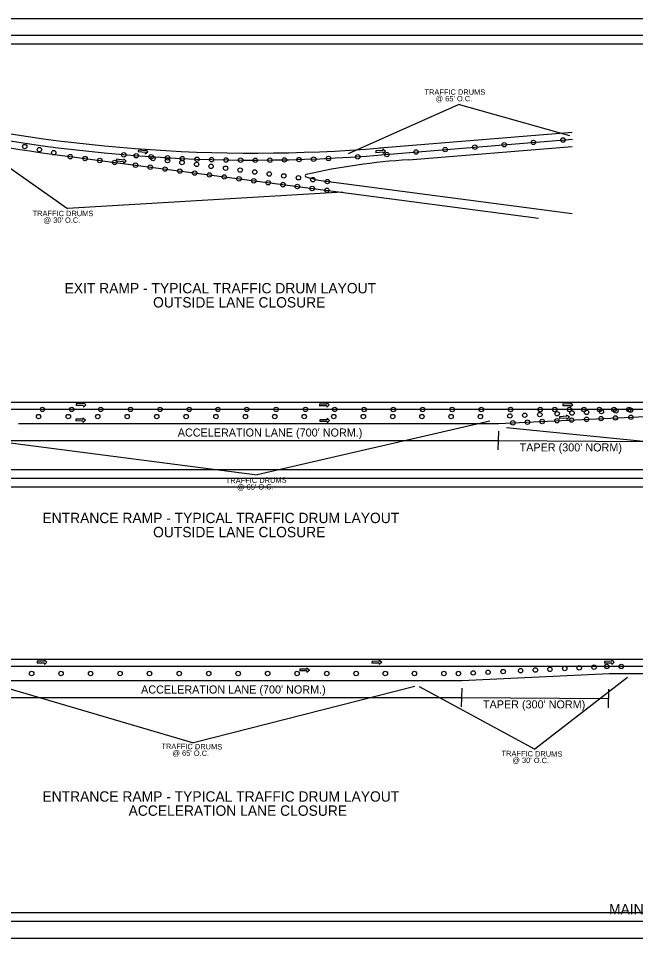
# Model space of a CAD drawing. Extents: x 13528 to 25043, y 7635 to 10612.
# Drawn here: x 18181 to 18896, y 9545 to 10612 of the extents above; entities that cross this region are included whole.
import ezdxf

# ---------------------------------------------------------------- set-up
doc = ezdxf.new("R2010")
doc.units = 0
for name, color, linetype in [('Default', 7, 'Continuous'), ('R_Border', 7, 'Continuous'), ('R_Border Plan-Plan', 7, 'Continuous'), ('R_Draft', 7, 'Continuous'), ('R_Revision Date Text', 7, 'Continuous')]:
    doc.layers.add(name, color=color, linetype=linetype)

# ---------------------------------------------------------------- blocks, each defined once
blk = doc.blocks.new('DOT')
at = {"layer": 'Default'}
blk.add_circle((-0.4, -0.3), 3.75, dxfattribs=at)
blk = doc.blocks.new('SARROW')
at = {"layer": 'Default'}
for p, q in [((15.6, 3.2), (-13.8, 3.2)), ((-13.8, 3.2), (-13.8, -2.8)), ((15.6, 8.2), (15.6, 3.2)), ((15.6, 8.2), (26, 0.2)), ((26, 0.2), (15.6, -7.8)), ((15.6, -2.8), (-13.8, -2.8)), ((15.6, -2.8), (15.6, -7.8))]:
    blk.add_line(p, q, dxfattribs=at)

msp = doc.modelspace()

# ---------------------------------------------------------------- linework, layer by layer
at = {"layer": 'Default'}
for p, q in [((18599.8, 10461.4), (18822.8, 10479.6)), ((18601.5, 10453.3), (18823.3, 10471.5)), ((18217.1, 10454.7), (18783.8, 10380.1)), ((18633.3, 10447.7), (18822.8, 10463.2)), ((18534.5, 10423.2), (18822.8, 10385.2)), ((18002.2, 10166.6), (19044, 10166.6)), ((18002, 10158.4), (19043.8, 10158.4)), ((18737.5, 10142.1), (18908.1, 10150.2)), ((18181, 10142), (18737.5, 10142.1)), ((18737.4, 10133.1), (18736.8, 10111.3)), ((18087.9, 10122.2), (18737.1, 10122.2)), ((17907.8, 9868.7), (19009.2, 9868.7)), ((17907.6, 9860.5), (19009, 9860.5)), ((18695, 9844.2), (18865.7, 9852.3)), ((18865.7, 9852.3), (19008.8, 9852.3)), ((18138.5, 9844.2), (18695, 9844.2)), ((18694.9, 9835.2), (18694.4, 9813.5)), ((18045.4, 9824.3), (18694.6, 9824.3)), ((18865.1, 9834), (18864.6, 9812.3))]:
    msp.add_line(p, q, dxfattribs=at)
for centre, major_axis, start_param, end_param in [((18454.4, 13048.2), (0, 2600.9), 2.945637, 3.209664), ((18454.4, 13048.2), (0, 2592.8), 2.945637, 3.209664), ((18454.4, 13048.2), (0, 2609.1), 2.94688, 3.032274), ((18680.7, 9372.1), (0, 1077.1), 0.052832, 0.186328), ((18514.6, 10429.2), (0, 1.36), 0.197268, 2.831699), ((18548, 10570.7), (0, -148.3), 6.00653, 6.174382)]:
    msp.add_ellipse(centre, major_axis=major_axis, ratio=0.833333, start_param=start_param, end_param=end_param, dxfattribs=at)
at = {"layer": 'R_Border'}
for p, q in [((18563.8, 10454.9), (18691.1, 10511.6)), ((18820.1, 10475.3), (18691.1, 10511.6)), ((18111.7, 10480), (18237.7, 10391.1)), ((18315.9, 10450.8), (18315.5, 10450.4)), ((18556.6, 10410), (18237.7, 10391.1)), ((18727.5, 10144.5), (18457.7, 10082.5)), ((18060.9, 10134), (18457.7, 10082.5)), ((18747, 10137.5), (18946.7, 10117.4)), ((18737.1, 10122.2), (18907.3, 10121)), ((18887, 9847.7), (18779.8, 9764.3)), ((18155.5, 9838.8), (18383.8, 9771.7)), ((18640.4, 9836.9), (18383.8, 9771.7)), ((18645.6, 9837), (18779.8, 9764.3)), ((18694.6, 9824.3), (18864.9, 9823.1))]:
    msp.add_line(p, q, dxfattribs=at)
at = {"layer": 'R_Border Plan-Plan'}
msp.add_line((17653.6, 10078.4), (19234.5, 10078.4), dxfattribs=at)
at = {"layer": 'R_Draft'}
for p, q in [((17653.6, 10592.1), (19234.5, 10592.1)), ((18416.2, 10590.8), (18416.2, 10590.8)), ((18416.2, 10590.8), (18416.2, 10590.8)), ((19234.5, 9564.8), (17653.6, 9564.8))]:
    msp.add_line(p, q, dxfattribs=at)
at = {"layer": 'R_Revision Date Text'}
for points in [[(17591.6, 10611.5), (19258.3, 10611.5), (19258.3, 9544.9), (17591.6, 9544.9)], [(19224.5, 10088.4), (17663.6, 10088.4), (17663.6, 10582.1), (18911.3, 10582.1), (18911.3, 10532.7), (18999, 10532.7), (19119.5, 10532.7), (19119.5, 10421), (19224.5, 10421)], [(17663.6, 10582.1), (18911.3, 10582.1), (18911.3, 10532.7), (18999, 10532.7), (19119.5, 10532.7), (19119.5, 10421), (19224.5, 10421), (19224.5, 9574.8), (17663.6, 9574.8)], [(17663.6, 10068.4), (19224.5, 10068.4), (19224.5, 9574.8), (17663.6, 9574.8)]]:
    msp.add_lwpolyline(points, close=True, dxfattribs=at)

# ---------------------------------------------------------------- block references
at = {"layer": 'R_Border', "xscale": 0.6809210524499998, "yscale": 0.6809210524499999}
for p in [(18188.6, 10463.2), (18710.4, 10462.5), (18744.5, 10465.3), (18778.3, 10468), (18812.6, 10470.8), (18205.6, 10459.6), (18222.2, 10456.1), (18241.3, 10451.5), (18303.4, 10453.6), (18317.8, 10452.6), (18335.1, 10451.3), (18574.6, 10451.3), (18608.4, 10453.9), (18642.2, 10456.9), (18676, 10459.7), (18258.5, 10449.3), (18275.6, 10447), (18292.8, 10444.8), (18317, 10441.6), (18337.2, 10449.2), (18354.1, 10447), (18354.2, 10450.1), (18370.9, 10444.7), (18371.2, 10449.2), (18387.8, 10442.5), (18388.3, 10448.5), (18405.2, 10448), (18422, 10447.6), (18438.9, 10447.4), (18455.8, 10447.3), (18472.8, 10447.4), (18489.6, 10447.7), (18506.5, 10448.1), (18523.5, 10448.6), (18540.7, 10449.4), (18334.1, 10439.3), (18351.3, 10437.1), (18368.4, 10434.8), (18385.6, 10432.5), (18402.7, 10430.3), (18404.6, 10440.3), (18421.4, 10438.1), (18438.3, 10435.9), (18455.2, 10433.7), (18472, 10431.4), (18419.9, 10428), (18437, 10425.8), (18454.1, 10423.5), (18470.8, 10421.3), (18488.8, 10429.2), (18505.9, 10427), (18522.6, 10424.8), (18539.4, 10422.6), (18488, 10419), (18504.6, 10416.9), (18521.8, 10414.6), (18538.9, 10412.5)]:
    msp.add_blockref('DOT', p, dxfattribs=at)
at = {"layer": 'R_Border'}
for name, p, xscale, yscale, rotation in [('SARROW', (18323.8, 10457.3), 0.2841392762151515, 0.3399546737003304, -5.657384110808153), ('SARROW', (18599.3, 10457.1), 0.2840002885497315, 0.3401210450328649, 4.632677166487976), ('SARROW', (18298.6, 10446.7), 0.2843459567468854, 0.3397075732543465, -6.906452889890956), ('SARROW', (18251.9, 10163.6), 0.2839678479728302, 0.3401599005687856, -0.3179055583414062), ('SARROW', (18534, 10163.4), 0.2840325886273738, 0.3400823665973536, 0.21294869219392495), ('SARROW', (18816.2, 10163.5), 0.2839581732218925, 0.3401714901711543, -0.402879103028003), ('DOT', (18209.1, 10158.5), 0.6809210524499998, 0.6809210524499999, -4.676990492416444), ('DOT', (18243, 10158.5), 0.6809210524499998, 0.6809210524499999, -4.676990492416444), ('DOT', (18276.7, 10158.5), 0.6809210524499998, 0.6809210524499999, -4.676990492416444), ('DOT', (18311.2, 10158.5), 0.6809210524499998, 0.6809210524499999, -4.676990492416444), ('DOT', (18345.5, 10158.5), 0.6809210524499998, 0.6809210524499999, -4.676990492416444), ('DOT', (18379.3, 10158.5), 0.6809210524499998, 0.6809210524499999, -4.676990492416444), ('DOT', (18412.6, 10158.5), 0.6809210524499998, 0.6809210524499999, -4.676990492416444), ('DOT', (18446, 10158.5), 0.6809210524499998, 0.6809210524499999, -4.676990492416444), ('DOT', (18480.1, 10158.5), 0.6809210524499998, 0.6809210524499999, -4.676990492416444), ('DOT', (18514.1, 10158.5), 0.6809210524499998, 0.6809210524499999, -4.676990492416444), ('DOT', (18547.9, 10158.5), 0.6809210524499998, 0.6809210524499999, -4.676990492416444), ('DOT', (18582, 10158.4), 0.6809210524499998, 0.6809210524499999, -4.676990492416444), ('DOT', (18615.9, 10158.4), 0.6809210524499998, 0.6809210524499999, -4.676990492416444), ('DOT', (18649.8, 10158.4), 0.6809210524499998, 0.6809210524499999, -4.676990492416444), ('DOT', (18684.1, 10158.4), 0.6809210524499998, 0.6809210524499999, -4.676990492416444), ('DOT', (18717.9, 10158.4), 0.6809210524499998, 0.6809210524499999, -4.676990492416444), ('DOT', (18751.8, 10158.4), 0.6809210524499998, 0.6809210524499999, -4.676990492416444), ('DOT', (18785.7, 10152.5), 0.6809210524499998, 0.6809210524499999, -4.676990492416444), ('DOT', (18786.2, 10158.4), 0.6809210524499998, 0.6809210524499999, -4.676990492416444), ('DOT', (18803.1, 10158.4), 0.6809210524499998, 0.6809210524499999, -4.676990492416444), ('DOT', (18805.8, 10153.5), 0.6809210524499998, 0.6809210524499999, -4.676990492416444), ('DOT', (18820, 10158.4), 0.6809210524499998, 0.6809210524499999, -4.676990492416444), ('DOT', (18823, 10154.3), 0.6809210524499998, 0.6809210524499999, -4.676990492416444), ('DOT', (18836.9, 10158.4), 0.6809210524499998, 0.6809210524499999, -4.676990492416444), ('DOT', (18839.9, 10155.1), 0.6809210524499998, 0.6809210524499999, -4.676990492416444), ('DOT', (18854.8, 10158.4), 0.6809210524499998, 0.6809210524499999, -4.676990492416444), ('DOT', (18857.1, 10155.9), 0.6809210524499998, 0.6809210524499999, -4.676990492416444), ('DOT', (18871.7, 10158.4), 0.6809210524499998, 0.6809210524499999, -4.676990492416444), ('DOT', (18873.9, 10156.7), 0.6809210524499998, 0.6809210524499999, -4.676990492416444), ('DOT', (18889, 10158.4), 0.6809210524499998, 0.6809210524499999, -4.676990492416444), ('DOT', (18891, 10157.6), 0.6809210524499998, 0.6809210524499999, -4.676990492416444), ('DOT', (18204.7, 10150.2), 0.6809210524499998, 0.6809210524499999, -4.676990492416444), ('DOT', (18239.1, 10150.2), 0.6809210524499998, 0.6809210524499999, -4.676990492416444), ('SARROW', (18251.4, 10145.8), 0.2839678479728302, 0.3401599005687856, -0.3179055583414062), ('DOT', (18273.2, 10150.2), 0.6809210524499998, 0.6809210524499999, -4.676990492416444), ('DOT', (18307.4, 10150.2), 0.6809210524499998, 0.6809210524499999, -4.676990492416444), ('DOT', (18341.6, 10150.2), 0.6809210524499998, 0.6809210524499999, -4.676990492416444), ('DOT', (18375.7, 10150.2), 0.6809210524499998, 0.6809210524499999, -4.676990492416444), ('DOT', (18410.2, 10150.2), 0.6809210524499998, 0.6809210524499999, -4.676990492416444), ('DOT', (18444.4, 10150.2), 0.6809210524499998, 0.6809210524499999, -4.676990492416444), ('DOT', (18478.4, 10150.2), 0.6809210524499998, 0.6809210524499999, -4.676990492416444), ('DOT', (18512.6, 10150.2), 0.6809210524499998, 0.6809210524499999, -4.676990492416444), ('SARROW', (18534.3, 10145.2), 0.2840325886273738, 0.3400823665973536, 0.21294869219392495), ('DOT', (18546.8, 10150.2), 0.6809210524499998, 0.6809210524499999, -4.676990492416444), ('DOT', (18581.1, 10150.2), 0.6809210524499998, 0.6809210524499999, -4.676990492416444), ('DOT', (18615.2, 10150.2), 0.6809210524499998, 0.6809210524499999, -4.676990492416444), ('DOT', (18649.1, 10150.2), 0.6809210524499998, 0.6809210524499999, -4.676990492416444), ('DOT', (18682.9, 10150.2), 0.6809210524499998, 0.6809210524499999, -4.676990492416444), ('DOT', (18716.9, 10150.2), 0.6809210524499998, 0.6809210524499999, -4.676990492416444), ('DOT', (18751, 10150.9), 0.6809210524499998, 0.6809210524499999, -4.676990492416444), ('DOT', (18754.5, 10142.9), 0.6809210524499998, 0.6809210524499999, -4.676990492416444), ('DOT', (18754.5, 10142.9), 0.6809210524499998, 0.6809210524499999, -4.676990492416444), ('DOT', (18768.2, 10151.7), 0.6809210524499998, 0.6809210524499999, -4.676990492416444), ('DOT', (18771.4, 10143.7), 0.6809210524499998, 0.6809210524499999, -4.676990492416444), ('DOT', (18788.4, 10144.5), 0.6809210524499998, 0.6809210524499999, -4.676990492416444), ('DOT', (18805.6, 10145.3), 0.6809210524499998, 0.6809210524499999, -4.676990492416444), ('SARROW', (18812.3, 10149), 0.2846173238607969, 0.33938368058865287, 3.589093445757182), ('DOT', (18822.6, 10146.1), 0.6809210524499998, 0.6809210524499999, -4.676990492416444), ('DOT', (18839.9, 10147), 0.6809210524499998, 0.6809210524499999, -4.676990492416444), ('DOT', (18856.7, 10147.8), 0.6809210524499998, 0.6809210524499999, -4.676990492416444), ('DOT', (18873.4, 10148.6), 0.6809210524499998, 0.6809210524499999, -4.676990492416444), ('DOT', (18891.3, 10149.4), 0.6809210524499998, 0.6809210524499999, -4.676990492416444), ('SARROW', (18206.7, 9865.2), 0.28398470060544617, 0.3401397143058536, -0.17370681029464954), ('SARROW', (18594.8, 9865.2), 0.2839135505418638, 0.34022495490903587, -0.8188905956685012), ('SARROW', (18864.4, 9865.2), 0.28414238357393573, 0.3399509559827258, 1.0011972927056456), ('SARROW', (18511, 9856.1), 0.2839135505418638, 0.34022495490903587, -0.8188905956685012), ('DOT', (18725.7, 9853.8), 0.6809210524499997, 0.6809210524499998, -4.676990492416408), ('DOT', (18743.2, 9854.6), 0.6809210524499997, 0.6809210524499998, -4.676990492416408), ('DOT', (18763.4, 9855.6), 0.6809210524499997, 0.6809210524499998, -4.676990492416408), ('DOT', (18780.5, 9856.4), 0.6809210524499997, 0.6809210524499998, -4.676990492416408), ('DOT', (18797.4, 9857.2), 0.6809210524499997, 0.6809210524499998, -4.676990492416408), ('DOT', (18814.6, 9858.1), 0.6809210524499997, 0.6809210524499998, -4.676990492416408), ('DOT', (18831.4, 9858.9), 0.6809210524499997, 0.6809210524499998, -4.676990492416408), ('DOT', (18848.6, 9859.7), 0.6809210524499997, 0.6809210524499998, -4.676990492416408), ('DOT', (18863.3, 9860.5), 0.6809210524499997, 0.6809210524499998, -4.676990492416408), ('DOT', (18880.1, 9860.5), 0.6809210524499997, 0.6809210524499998, -4.676990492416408), ('DOT', (18196.6, 9852.3), 0.6809210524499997, 0.6809210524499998, -4.676990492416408), ('DOT', (18230.7, 9852.3), 0.6809210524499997, 0.6809210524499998, -4.676990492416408), ('DOT', (18264.9, 9852.3), 0.6809210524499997, 0.6809210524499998, -4.676990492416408), ('DOT', (18299.1, 9852.3), 0.6809210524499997, 0.6809210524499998, -4.676990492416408), ('DOT', (18333.2, 9852.3), 0.6809210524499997, 0.6809210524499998, -4.676990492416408), ('DOT', (18367.7, 9852.3), 0.6809210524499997, 0.6809210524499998, -4.676990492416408), ('DOT', (18401.9, 9852.3), 0.6809210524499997, 0.6809210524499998, -4.676990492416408), ('DOT', (18436, 9852.3), 0.6809210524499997, 0.6809210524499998, -4.676990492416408), ('DOT', (18470.2, 9852.3), 0.6809210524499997, 0.6809210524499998, -4.676990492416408), ('DOT', (18504.3, 9852.3), 0.6809210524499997, 0.6809210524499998, -4.676990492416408), ('DOT', (18538.7, 9852.3), 0.6809210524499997, 0.6809210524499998, -4.676990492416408), ('DOT', (18572.8, 9852.3), 0.6809210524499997, 0.6809210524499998, -4.676990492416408), ('DOT', (18606.6, 9852.3), 0.6809210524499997, 0.6809210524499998, -4.676990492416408), ('DOT', (18640.4, 9852.3), 0.6809210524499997, 0.6809210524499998, -4.676990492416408), ('DOT', (18674.5, 9852.3), 0.6809210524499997, 0.6809210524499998, -4.676990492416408), ('DOT', (18691.3, 9852.3), 0.6809210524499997, 0.6809210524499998, -4.676990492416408), ('DOT', (18708.5, 9853), 0.6809210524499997, 0.6809210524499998, -4.676990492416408)]:
    msp.add_blockref(name, p, dxfattribs=dict(at, xscale=xscale, yscale=yscale, rotation=rotation))

# ---------------------------------------------------------------- texts
at = {"layer": 'Default'}
for s, rotation, p in [("ACCELERATION LANE (700' NORM.)", 0.0037, (18365.7, 10126.8)), ("TAPER (300' NORM)", 0.0038, (18762, 10109.6)), ("ACCELERATION LANE (700' NORM.)", 0.0037, (18323.2, 9828.9)), ("TAPER (300' NORM)", 0.0038, (18719.5, 9811.7))]:
    msp.add_text(s, height=9.368, rotation=rotation, dxfattribs=at).set_placement(p)
at = {"layer": 'R_Border'}
for s, height, p in [('TRAFFIC DRUMS ', 6.25, (18651.7, 10523)), ("@ 65' O.C.", 6.25, (18664.6, 10515.4)), ('TRAFFIC DRUMS ', 6.25, (18197.4, 10382.3)), ("@ 30' O.C.", 6.25, (18210.2, 10374.6)), ('EXIT RAMP - TYPICAL TRAFFIC DRUM LAYOUT', 12, (18234.5, 10292.8)), ('OUTSIDE LANE CLOSURE', 12, (18337.1, 10276.4)), ('ENTRANCE RAMP - TYPICAL TRAFFIC DRUM LAYOUT', 12, (18208.8, 10026.5)), ('OUTSIDE LANE CLOSURE', 12, (18337.1, 10010.1)), ('ENTRANCE RAMP - TYPICAL TRAFFIC DRUM LAYOUT', 12, (18208.8, 9703.6)), ('ACCELERATION LANE CLOSURE', 12, (18308.7, 9687.2))]:
    msp.add_text(s, height=height, dxfattribs=at).set_placement(p)
for s, rotation, p in [('TRAFFIC DRUMS ', 0.6305, (18421.4, 10072.6)), ("@ 65' O.C.", 0.6305, (18434.4, 10065.1)), ('TRAFFIC DRUMS ', 359.4579, (18346.7, 9764.7)), ("@ 65' O.C.", 359.4579, (18359.5, 9756.9)), ('TRAFFIC DRUMS ', 359.4579, (18741, 9756.4)), ("@ 30' O.C.", 359.4579, (18753.6, 9748.6))]:
    msp.add_text(s, height=6.25, rotation=rotation, dxfattribs=at).set_placement(p)
at = {"layer": 'R_Border Plan-Plan'}
msp.add_text('MAINTENANCE OF TRAFFIC DETAILS', height=12, dxfattribs=at).set_placement((18865.7, 9573))

doc.saveas('drawing.dxf')
